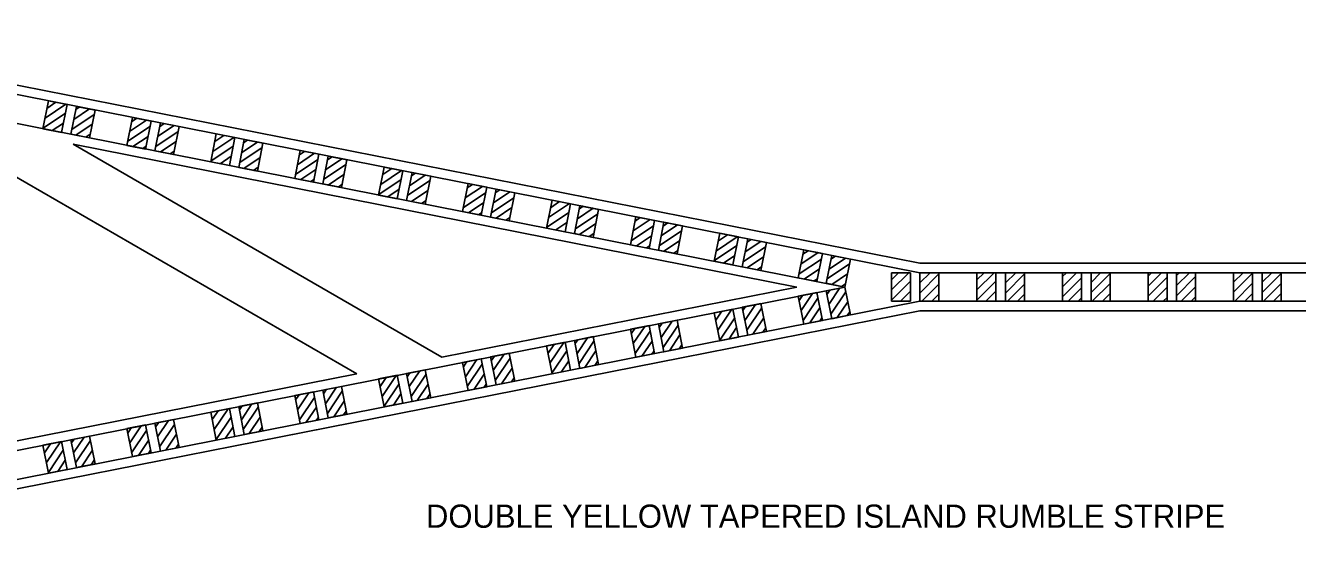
# Model space of a CAD drawing. Extents: x 49976.2 to 50021, y 49987.6 to 50011.4.
# Drawn here: x 50005.455 to 50009.846, y 49993.716 to 49995.521 of the extents above; entities that cross this region are included whole.
import ezdxf

# ---------------------------------------------------------------- set-up
doc = ezdxf.new("R2010")
doc.units = 0
doc.layers.add('Level 1', color=7, linetype='Continuous')
doc.layers.add('Level 2', color=7, linetype='Continuous')

msp = doc.modelspace()

# ---------------------------------------------------------------- linework, layer by layer
at = {"layer": 'Level 1'}
for p, q in [((50008.5427, 49994.7003), (50004.3823, 49995.521)), ((50008.5427, 49994.6675), (50004.3761, 49995.4895)), ((50008.2835, 49994.6183), (50004.357, 49995.3929)), ((50005.0225, 49995.2288), (50006.5989, 49994.3187)), ((50005.5156, 49995.1643), (50005.5347, 49995.2609)), ((50005.5949, 49995.249), (50005.5228, 49995.2007)), ((50005.5607, 49995.2557), (50005.5296, 49995.2349)), ((50005.5347, 49995.2609), (50005.5991, 49995.2482)), ((50005.5991, 49995.2482), (50005.58, 49995.1516)), ((50005.6122, 49995.1453), (50005.6313, 49995.2418)), ((50005.6766, 49995.2329), (50005.6223, 49995.1964)), ((50005.6425, 49995.2396), (50005.629, 49995.2306)), ((50005.6313, 49995.2418), (50005.6956, 49995.2291)), ((50005.6956, 49995.2291), (50005.6766, 49995.1326)), ((50005.5932, 49995.2182), (50005.5161, 49995.1666)), ((50005.6926, 49995.214), (50005.6156, 49995.1623)), ((50005.8053, 49995.1072), (50005.8244, 49995.2037)), ((50005.8736, 49995.194), (50005.8147, 49995.1545)), ((50005.8394, 49995.2008), (50005.8214, 49995.1887)), ((50005.8244, 49995.2037), (50005.8887, 49995.191)), ((50005.8887, 49995.191), (50005.8697, 49995.0945)), ((50005.9019, 49995.0881), (50005.9209, 49995.1847)), ((50005.9209, 49995.1847), (50005.9853, 49995.172)), ((50005.58, 49995.1516), (50005.5156, 49995.1643)), ((50005.5864, 49995.1841), (50005.5475, 49995.158)), ((50005.6766, 49995.1326), (50005.6122, 49995.1453)), ((50005.6859, 49995.1798), (50005.6293, 49995.1419)), ((50005.6792, 49995.1457), (50005.6635, 49995.1352)), ((50005.885, 49995.1721), (50005.8079, 49995.1204)), ((50005.9819, 49995.1549), (50005.9048, 49995.1032)), ((50005.9682, 49995.1754), (50005.9116, 49995.1374)), ((50005.9341, 49995.1821), (50005.9183, 49995.1715)), ((50005.9853, 49995.172), (50005.9662, 49995.0754)), ((50006.095, 49995.05), (50006.114, 49995.1466)), ((50006.1401, 49995.1415), (50006.1089, 49995.1206)), ((50006.114, 49995.1466), (50006.1784, 49995.1339)), ((50008.1174, 49994.6183), (50005.6205, 49995.1109)), ((50005.6205, 49995.1109), (50006.8923, 49994.3766)), ((50005.8697, 49995.0945), (50005.8053, 49995.1072)), ((50005.8783, 49995.1379), (50005.8262, 49995.1031)), ((50005.8715, 49995.1038), (50005.8604, 49995.0963)), ((50005.9752, 49995.1208), (50005.9209, 49995.0844)), ((50006.1725, 49995.104), (50006.0954, 49995.0523)), ((50006.1742, 49995.1347), (50006.1022, 49995.0864)), ((50006.1784, 49995.1339), (50006.1593, 49995.0373)), ((50006.1915, 49995.031), (50006.2106, 49995.1275)), ((50006.272, 49995.0997), (50006.1949, 49995.048)), ((50006.256, 49995.1186), (50006.2016, 49995.0822)), ((50006.2218, 49995.1253), (50006.2084, 49995.1163)), ((50006.2106, 49995.1275), (50006.2749, 49995.1148)), ((50006.2749, 49995.1148), (50006.2559, 49995.0183)), ((50005.9662, 49995.0754), (50005.9019, 49995.0881)), ((50005.9684, 49995.0866), (50005.9551, 49995.0776)), ((50006.1658, 49995.0698), (50006.1269, 49995.0438)), ((50006.2652, 49995.0656), (50006.2086, 49995.0276)), ((50006.3846, 49994.9929), (50006.4037, 49995.0895)), ((50006.4643, 49995.0578), (50006.3872, 49995.0061)), ((50006.4529, 49995.0797), (50006.394, 49995.0403)), ((50006.4187, 49995.0865), (50006.4007, 49995.0744)), ((50006.4037, 49995.0895), (50006.4681, 49995.0768)), ((50006.4681, 49995.0768), (50006.449, 49994.9802)), ((50006.4812, 49994.9739), (50006.5002, 49995.0704)), ((50006.5476, 49995.0611), (50006.4909, 49995.0231)), ((50006.5134, 49995.0678), (50006.4976, 49995.0572)), ((50006.5002, 49995.0704), (50006.5646, 49995.0577)), ((50006.5646, 49995.0577), (50006.5456, 49994.9612)), ((50006.1593, 49995.0373), (50006.095, 49995.05)), ((50006.2559, 49995.0183), (50006.1915, 49995.031)), ((50006.2585, 49995.0314), (50006.2428, 49995.0209)), ((50006.4576, 49995.0237), (50006.4056, 49994.9888)), ((50006.5612, 49995.0406), (50006.4842, 49994.9889)), ((50006.6743, 49994.9358), (50006.6933, 49995.0323)), ((50006.7535, 49995.0204), (50006.6815, 49994.9721)), ((50006.7194, 49995.0272), (50006.6882, 49995.0063)), ((50006.6933, 49995.0323), (50006.7577, 49995.0196)), ((50006.7577, 49995.0196), (50006.7387, 49994.9231)), ((50006.7709, 49994.9167), (50006.7899, 49995.0133)), ((50006.8012, 49995.011), (50006.7877, 49995.002)), ((50006.7899, 49995.0133), (50006.8543, 49995.0006)), ((50006.449, 49994.9802), (50006.3846, 49994.9929)), ((50006.4508, 49994.9895), (50006.4397, 49994.982)), ((50006.5456, 49994.9612), (50006.4812, 49994.9739)), ((50006.5545, 49995.0065), (50006.5002, 49994.9701)), ((50006.5478, 49994.9723), (50006.5344, 49994.9634)), ((50006.7518, 49994.9897), (50006.6747, 49994.938)), ((50006.8513, 49994.9854), (50006.7742, 49994.9337)), ((50006.8353, 49995.0043), (50006.7809, 49994.9679)), ((50006.8543, 49995.0006), (50006.8352, 49994.904)), ((50006.964, 49994.8786), (50006.983, 49994.9752)), ((50007.0322, 49994.9655), (50006.9733, 49994.926)), ((50006.9981, 49994.9722), (50006.98, 49994.9601)), ((50006.983, 49994.9752), (50007.0474, 49994.9625)), ((50006.7387, 49994.9231), (50006.6743, 49994.9358)), ((50006.7451, 49994.9555), (50006.7062, 49994.9295)), ((50006.8445, 49994.9513), (50006.788, 49994.9133)), ((50007.0436, 49994.9435), (50006.9666, 49994.8918)), ((50007.0474, 49994.9625), (50007.0283, 49994.8659)), ((50007.0605, 49994.8596), (50007.0796, 49994.9561)), ((50007.1406, 49994.9263), (50007.0635, 49994.8746)), ((50007.1269, 49994.9468), (50007.0702, 49994.9088)), ((50007.0928, 49994.9535), (50007.077, 49994.9429)), ((50007.0796, 49994.9561), (50007.1439, 49994.9434)), ((50007.1439, 49994.9434), (50007.1249, 49994.8469)), ((50006.8352, 49994.904), (50006.7709, 49994.9167)), ((50006.8378, 49994.9171), (50006.8221, 49994.9066)), ((50007.0283, 49994.8659), (50006.964, 49994.8786)), ((50007.0369, 49994.9094), (50006.9849, 49994.8745)), ((50007.1338, 49994.8922), (50007.0796, 49994.8558)), ((50007.2536, 49994.8215), (50007.2727, 49994.918)), ((50007.3328, 49994.9062), (50007.2608, 49994.8579)), ((50007.2987, 49994.9129), (50007.2675, 49994.892)), ((50007.2727, 49994.918), (50007.337, 49994.9053)), ((50007.337, 49994.9053), (50007.318, 49994.8088)), ((50007.3502, 49994.8024), (50007.3692, 49994.899)), ((50007.4146, 49994.89), (50007.3603, 49994.8536)), ((50007.3805, 49994.8968), (50007.367, 49994.8877)), ((50007.3692, 49994.899), (50007.4336, 49994.8863)), ((50007.4336, 49994.8863), (50007.4145, 49994.7897)), ((50007.0302, 49994.8752), (50007.019, 49994.8678)), ((50007.1249, 49994.8469), (50007.0605, 49994.8596)), ((50007.1271, 49994.858), (50007.1137, 49994.8491)), ((50007.3311, 49994.8754), (50007.2541, 49994.8237)), ((50007.3244, 49994.8413), (50007.2855, 49994.8152)), ((50007.4306, 49994.8711), (50007.3535, 49994.8195)), ((50007.4239, 49994.837), (50007.3673, 49994.799)), ((50007.5433, 49994.7643), (50007.5623, 49994.8609)), ((50007.6115, 49994.8512), (50007.5526, 49994.8117)), ((50007.5774, 49994.8579), (50007.5594, 49994.8458)), ((50007.5623, 49994.8609), (50007.6267, 49994.8482)), ((50007.6267, 49994.8482), (50007.6077, 49994.7516)), ((50007.6398, 49994.7453), (50007.6589, 49994.8418)), ((50007.6721, 49994.8392), (50007.6563, 49994.8286)), ((50007.6589, 49994.8418), (50007.7233, 49994.8291)), ((50007.318, 49994.8088), (50007.2536, 49994.8215)), ((50007.4145, 49994.7897), (50007.3502, 49994.8024)), ((50007.4171, 49994.8028), (50007.4014, 49994.7923)), ((50007.623, 49994.8292), (50007.5459, 49994.7775)), ((50007.6162, 49994.7951), (50007.5642, 49994.7602)), ((50007.7199, 49994.812), (50007.6428, 49994.7604)), ((50007.7062, 49994.8325), (50007.6495, 49994.7945)), ((50007.7233, 49994.8291), (50007.7042, 49994.7326)), ((50007.8329, 49994.7072), (50007.852, 49994.8037)), ((50007.9122, 49994.7919), (50007.8401, 49994.7436)), ((50007.878, 49994.7986), (50007.8469, 49994.7777)), ((50007.852, 49994.8037), (50007.9164, 49994.791)), ((50007.9164, 49994.791), (50007.8973, 49994.6945)), ((50007.6077, 49994.7516), (50007.5433, 49994.7643)), ((50007.6095, 49994.7609), (50007.5983, 49994.7535)), ((50007.7042, 49994.7326), (50007.6398, 49994.7453)), ((50007.7131, 49994.7779), (50007.6589, 49994.7415)), ((50007.9105, 49994.7611), (50007.8334, 49994.7094)), ((50007.9295, 49994.6881), (50007.9486, 49994.7847)), ((50008.0099, 49994.7568), (50007.9329, 49994.7052)), ((50007.9939, 49994.7757), (50007.9396, 49994.7393)), ((50007.9598, 49994.7825), (50007.9463, 49994.7734)), ((50007.9486, 49994.7847), (50008.0129, 49994.772)), ((50008.0129, 49994.772), (50007.9939, 49994.6754)), ((50008.1226, 49994.65), (50008.1417, 49994.7466)), ((50008.1417, 49994.7466), (50008.206, 49994.7339)), ((50007.7064, 49994.7438), (50007.693, 49994.7348)), ((50007.8973, 49994.6945), (50007.8329, 49994.7072)), ((50007.9037, 49994.727), (50007.8648, 49994.7009)), ((50008.0032, 49994.7227), (50007.9466, 49994.6848)), ((50008.2023, 49994.7149), (50008.1252, 49994.6633)), ((50008.1909, 49994.7369), (50008.132, 49994.6974)), ((50008.1567, 49994.7436), (50008.1387, 49994.7315)), ((50008.206, 49994.7339), (50008.187, 49994.6373)), ((50008.2192, 49994.631), (50008.2382, 49994.7276)), ((50008.2855, 49994.7182), (50008.2289, 49994.6802)), ((50008.2514, 49994.7249), (50008.2356, 49994.7144)), ((50008.2382, 49994.7276), (50008.3026, 49994.7149)), ((50008.3026, 49994.7149), (50008.2835, 49994.6183)), ((50007.9939, 49994.6754), (50007.9295, 49994.6881)), ((50007.9965, 49994.6886), (50007.9808, 49994.678)), ((50008.1956, 49994.6808), (50008.1435, 49994.6459)), ((50008.2992, 49994.6977), (50008.2221, 49994.6461)), ((50008.2925, 49994.6636), (50008.2382, 49994.6272)), ((50008.4443, 49994.5691), (50008.4443, 49994.6675)), ((50008.4443, 49994.6675), (50008.5099, 49994.6675)), ((50008.4443, 49994.608), (50008.5038, 49994.6675)), ((50008.4443, 49994.6428), (50008.469, 49994.6675)), ((50008.5099, 49994.6675), (50008.5099, 49994.5691)), ((50008.5427, 49994.7003), (50012.0505, 49994.7003)), ((50008.5427, 49994.6675), (50012.0505, 49994.6675)), ((50008.5427, 49994.5691), (50008.5427, 49994.6675)), ((50008.5427, 49994.6675), (50008.6083, 49994.6675)), ((50008.5427, 49994.6323), (50008.5779, 49994.6675)), ((50008.5427, 49994.6671), (50008.5431, 49994.6675)), ((50008.5427, 49994.5975), (50008.6083, 49994.6632)), ((50008.6083, 49994.6675), (50008.6083, 49994.5691)), ((50008.7395, 49994.5691), (50008.7395, 49994.6675)), ((50008.7395, 49994.6675), (50008.8051, 49994.6675)), ((50008.7395, 49994.608), (50008.799, 49994.6675)), ((50008.7395, 49994.6428), (50008.7642, 49994.6675)), ((50008.8051, 49994.6675), (50008.8051, 49994.5691)), ((50008.8379, 49994.5691), (50008.8379, 49994.6675)), ((50008.8379, 49994.6675), (50008.9035, 49994.6675)), ((50008.8379, 49994.6323), (50008.8731, 49994.6675)), ((50008.8379, 49994.6671), (50008.8383, 49994.6675)), ((50008.8379, 49994.5975), (50008.9035, 49994.6632)), ((50008.9035, 49994.6675), (50008.9035, 49994.5691)), ((50009.0347, 49994.5691), (50009.0347, 49994.6675)), ((50009.0347, 49994.6675), (50009.1004, 49994.6675)), ((50009.0347, 49994.6194), (50009.0829, 49994.6675)), ((50009.0347, 49994.6541), (50009.0481, 49994.6675)), ((50009.1004, 49994.6675), (50009.1004, 49994.5691)), ((50009.1332, 49994.5691), (50009.1332, 49994.6675)), ((50009.1332, 49994.6675), (50009.1988, 49994.6675)), ((50009.1332, 49994.6344), (50009.1663, 49994.6675)), ((50009.1332, 49994.5996), (50009.1988, 49994.6652)), ((50009.1988, 49994.6675), (50009.1988, 49994.5691)), ((50009.33, 49994.5691), (50009.33, 49994.6675)), ((50009.33, 49994.6675), (50009.3956, 49994.6675)), ((50009.33, 49994.6213), (50009.3762, 49994.6675)), ((50009.33, 49994.6561), (50009.3414, 49994.6675)), ((50009.3956, 49994.6675), (50009.3956, 49994.5691)), ((50009.4284, 49994.5691), (50009.4284, 49994.6675)), ((50009.4284, 49994.6675), (50009.494, 49994.6675)), ((50009.4284, 49994.6232), (50009.4727, 49994.6675)), ((50009.4284, 49994.658), (50009.4379, 49994.6675)), ((50009.494, 49994.6675), (50009.494, 49994.5691)), ((50009.6252, 49994.5691), (50009.6252, 49994.6675)), ((50009.6252, 49994.6675), (50009.6908, 49994.6675)), ((50009.6252, 49994.6351), (50009.6577, 49994.6675)), ((50009.6252, 49994.6003), (50009.6908, 49994.6659)), ((50009.6908, 49994.6675), (50009.6908, 49994.5691)), ((50009.7237, 49994.5691), (50009.7237, 49994.6675)), ((50009.7237, 49994.6675), (50009.7893, 49994.6675)), ((50009.7237, 49994.6345), (50009.7567, 49994.6675)), ((50009.7237, 49994.5997), (50009.7893, 49994.6653)), ((50009.7893, 49994.6675), (50009.7893, 49994.5691)), ((50008.2835, 49994.6183), (50004.357, 49993.8437)), ((50008.1174, 49994.6183), (50006.8923, 49994.3766)), ((50008.187, 49994.6373), (50008.1226, 49994.65)), ((50008.1888, 49994.6467), (50008.1777, 49994.6392)), ((50008.2835, 49994.6183), (50008.2192, 49994.631)), ((50008.2192, 49994.6056), (50008.2835, 49994.6183)), ((50008.2665, 49994.6149), (50008.2285, 49994.5583)), ((50008.2857, 49994.6295), (50008.2724, 49994.6205)), ((50008.2835, 49994.6183), (50008.3026, 49994.5217)), ((50008.4443, 49994.5732), (50008.5099, 49994.6388)), ((50008.549, 49994.5691), (50008.6083, 49994.6284)), ((50008.7395, 49994.5732), (50008.8051, 49994.6388)), ((50008.8443, 49994.5691), (50008.9035, 49994.6284)), ((50009.0347, 49994.5846), (50009.1004, 49994.6502)), ((50009.0541, 49994.5691), (50009.1004, 49994.6154)), ((50009.1374, 49994.5691), (50009.1988, 49994.6304)), ((50009.33, 49994.5865), (50009.3956, 49994.6521)), ((50009.3474, 49994.5691), (50009.3956, 49994.6174)), ((50009.4284, 49994.5884), (50009.494, 49994.654)), ((50009.4439, 49994.5691), (50009.494, 49994.6193)), ((50009.6289, 49994.5691), (50009.6908, 49994.6311)), ((50009.7279, 49994.5691), (50009.7893, 49994.6305)), ((50008.1226, 49994.5866), (50008.187, 49994.5993)), ((50008.1417, 49994.49), (50008.1226, 49994.5866)), ((50008.1377, 49994.5895), (50008.1256, 49994.5715)), ((50008.1718, 49994.5963), (50008.1323, 49994.5374)), ((50008.1907, 49994.5803), (50008.1391, 49994.5032)), ((50008.187, 49994.5993), (50008.206, 49994.5027)), ((50008.2382, 49994.509), (50008.2192, 49994.6056)), ((50008.2324, 49994.6082), (50008.2218, 49994.5924)), ((50008.2869, 49994.6012), (50008.2352, 49994.5241)), ((50008.475, 49994.5691), (50008.5099, 49994.604)), ((50008.5838, 49994.5691), (50008.6083, 49994.5936)), ((50008.7702, 49994.5691), (50008.8051, 49994.604)), ((50008.8791, 49994.5691), (50008.9035, 49994.5936)), ((50009.0889, 49994.5691), (50009.1004, 49994.5806)), ((50009.1722, 49994.5691), (50009.1988, 49994.5956)), ((50009.3821, 49994.5691), (50009.3956, 49994.5826)), ((50009.4787, 49994.5691), (50009.494, 49994.5845)), ((50009.6637, 49994.5691), (50009.6908, 49994.5963)), ((50009.7627, 49994.5691), (50009.7893, 49994.5957)), ((50008.5427, 49994.5691), (50004.376, 49993.7471)), ((50008.5427, 49994.5363), (50004.3823, 49993.7156)), ((50007.8329, 49994.5294), (50007.8973, 49994.5421)), ((50007.852, 49994.4329), (50007.8329, 49994.5294)), ((50007.859, 49994.5345), (50007.8381, 49994.5034)), ((50007.8931, 49994.5413), (50007.8448, 49994.4692)), ((50007.8973, 49994.5421), (50007.9164, 49994.4456)), ((50007.9295, 49994.5485), (50007.9939, 49994.5612)), ((50007.9486, 49994.4519), (50007.9295, 49994.5485)), ((50007.9408, 49994.5507), (50007.9317, 49994.5372)), ((50007.9749, 49994.5574), (50007.9385, 49994.5031)), ((50007.9969, 49994.546), (50007.9452, 49994.4689)), ((50007.9939, 49994.5612), (50008.0129, 49994.4646)), ((50008.1975, 49994.5461), (50008.1626, 49994.4941)), ((50008.2936, 49994.5671), (50008.2573, 49994.5128)), ((50008.3004, 49994.5329), (50008.2914, 49994.5195)), ((50008.5099, 49994.5691), (50008.4443, 49994.5691)), ((50008.5098, 49994.5691), (50008.5099, 49994.5692)), ((50008.5427, 49994.5691), (50012.0505, 49994.5691)), ((50008.6083, 49994.5691), (50008.5427, 49994.5691)), ((50008.5427, 49994.5363), (50012.0505, 49994.5363)), ((50008.8051, 49994.5691), (50008.7395, 49994.5691)), ((50008.805, 49994.5691), (50008.8051, 49994.5692)), ((50008.9035, 49994.5691), (50008.8379, 49994.5691)), ((50009.1004, 49994.5691), (50009.0347, 49994.5691)), ((50009.1988, 49994.5691), (50009.1332, 49994.5691)), ((50009.3956, 49994.5691), (50009.33, 49994.5691)), ((50009.494, 49994.5691), (50009.4284, 49994.5691)), ((50009.6908, 49994.5691), (50009.6252, 49994.5691)), ((50009.7893, 49994.5691), (50009.7237, 49994.5691)), ((50007.5433, 49994.4723), (50007.6077, 49994.485)), ((50007.5925, 49994.482), (50007.553, 49994.4231)), ((50007.6077, 49994.485), (50007.6267, 49994.3884)), ((50007.6398, 49994.4913), (50007.7042, 49994.504)), ((50007.6589, 49994.3948), (50007.6398, 49994.4913)), ((50007.653, 49994.4939), (50007.6424, 49994.4781)), ((50007.6872, 49994.5007), (50007.6492, 49994.444)), ((50007.7076, 49994.4869), (50007.6559, 49994.4098)), ((50007.7042, 49994.504), (50007.7233, 49994.4075)), ((50007.9032, 49994.5122), (50007.8516, 49994.4351)), ((50008.0036, 49994.5119), (50007.9657, 49994.4553)), ((50008.206, 49994.5027), (50008.1417, 49994.49)), ((50008.2042, 49994.512), (50008.1967, 49994.5009)), ((50008.3026, 49994.5217), (50008.2382, 49994.509)), ((50007.3502, 49994.4342), (50007.4145, 49994.4469)), ((50007.3956, 49994.4431), (50007.3591, 49994.3888)), ((50007.4145, 49994.4469), (50007.4336, 49994.3503)), ((50007.5623, 49994.3757), (50007.5433, 49994.4723)), ((50007.5583, 49994.4752), (50007.5463, 49994.4572)), ((50007.6114, 49994.466), (50007.5597, 49994.3889)), ((50007.7143, 49994.4528), (50007.6779, 49994.3985)), ((50007.9164, 49994.4456), (50007.852, 49994.4329)), ((50007.91, 49994.478), (50007.8839, 49994.4391)), ((50008.0129, 49994.4646), (50007.9486, 49994.4519)), ((50008.0103, 49994.4777), (50007.9998, 49994.462)), ((50007.2536, 49994.4151), (50007.318, 49994.4278)), ((50007.2727, 49994.3186), (50007.2536, 49994.4151)), ((50007.2797, 49994.4203), (50007.2588, 49994.3891)), ((50007.3138, 49994.427), (50007.2655, 49994.355)), ((50007.3239, 49994.3979), (50007.2722, 49994.3208)), ((50007.318, 49994.4278), (50007.337, 49994.3313)), ((50007.3692, 49994.3376), (50007.3502, 49994.4342)), ((50007.3614, 49994.4364), (50007.3524, 49994.4229)), ((50007.4175, 49994.4317), (50007.3659, 49994.3546)), ((50007.4243, 49994.3976), (50007.3863, 49994.341)), ((50007.6181, 49994.4319), (50007.5832, 49994.3798)), ((50007.6249, 49994.3977), (50007.6174, 49994.3866)), ((50007.7233, 49994.4075), (50007.6589, 49994.3948)), ((50007.7211, 49994.4186), (50007.7121, 49994.4053)), ((50006.964, 49994.358), (50007.0283, 49994.3707)), ((50006.983, 49994.2614), (50006.964, 49994.358)), ((50006.979, 49994.361), (50006.9669, 49994.3429)), ((50007.0132, 49994.3677), (50006.9737, 49994.3088)), ((50007.0321, 49994.3517), (50006.9804, 49994.2746)), ((50007.0283, 49994.3707), (50007.0474, 49994.2741)), ((50007.0605, 49994.377), (50007.1249, 49994.3897)), ((50007.0796, 49994.2805), (50007.0605, 49994.377)), ((50007.0737, 49994.3796), (50007.0631, 49994.3638)), ((50007.1079, 49994.3864), (50007.0699, 49994.3297)), ((50007.1283, 49994.3726), (50007.0766, 49994.2956)), ((50007.1249, 49994.3897), (50007.1439, 49994.2932)), ((50007.3306, 49994.3638), (50007.3046, 49994.3249)), ((50007.4336, 49994.3503), (50007.3692, 49994.3376)), ((50007.431, 49994.3634), (50007.4205, 49994.3477)), ((50007.6267, 49994.3884), (50007.5623, 49994.3757)), ((50006.5989, 49994.3187), (50004.3508, 49993.8752)), ((50006.6743, 49994.3008), (50006.7387, 49994.3135)), ((50006.7345, 49994.3127), (50006.6862, 49994.2407)), ((50006.7387, 49994.3135), (50006.7577, 49994.217)), ((50006.7709, 49994.3199), (50006.8352, 49994.3326)), ((50006.7899, 49994.2233), (50006.7709, 49994.3199)), ((50006.7821, 49994.3221), (50006.7731, 49994.3086)), ((50006.8162, 49994.3288), (50006.7798, 49994.2745)), ((50006.8382, 49994.3174), (50006.7865, 49994.2404)), ((50006.8352, 49994.3326), (50006.8543, 49994.236)), ((50007.0388, 49994.3176), (50007.0039, 49994.2656)), ((50007.135, 49994.3385), (50007.0986, 49994.2842)), ((50007.337, 49994.3313), (50007.2727, 49994.3186)), ((50006.4812, 49994.2627), (50006.5456, 49994.2754)), ((50006.5002, 49994.1662), (50006.4812, 49994.2627)), ((50006.4944, 49994.2653), (50006.4838, 49994.2495)), ((50006.5285, 49994.2721), (50006.4905, 49994.2154)), ((50006.5456, 49994.2754), (50006.5646, 49994.1789)), ((50006.6933, 49994.2043), (50006.6743, 49994.3008)), ((50006.7003, 49994.306), (50006.6794, 49994.2748)), ((50006.7446, 49994.2836), (50006.6929, 49994.2065)), ((50006.8449, 49994.2833), (50006.807, 49994.2267)), ((50007.0474, 49994.2741), (50006.983, 49994.2614)), ((50007.0455, 49994.2834), (50007.0381, 49994.2723)), ((50007.1439, 49994.2932), (50007.0796, 49994.2805)), ((50007.1417, 49994.3044), (50007.1328, 49994.291)), ((50006.1915, 49994.2056), (50006.2559, 49994.2183)), ((50006.2559, 49994.2183), (50006.2749, 49994.1217)), ((50006.3846, 49994.2437), (50006.449, 49994.2564)), ((50006.4037, 49994.1471), (50006.3846, 49994.2437)), ((50006.3997, 49994.2467), (50006.3876, 49994.2286)), ((50006.4338, 49994.2534), (50006.3943, 49994.1945)), ((50006.4527, 49994.2374), (50006.4011, 49994.1604)), ((50006.449, 49994.2564), (50006.4681, 49994.1598)), ((50006.5489, 49994.2583), (50006.4973, 49994.1813)), ((50006.5557, 49994.2242), (50006.5193, 49994.1699)), ((50006.7513, 49994.2495), (50006.7252, 49994.2106)), ((50006.8543, 49994.236), (50006.7899, 49994.2233)), ((50006.8517, 49994.2492), (50006.8411, 49994.2334)), ((50006.095, 49994.1866), (50006.1593, 49994.1993)), ((50006.114, 49994.09), (50006.095, 49994.1866)), ((50006.121, 49994.1917), (50006.1001, 49994.1605)), ((50006.1551, 49994.1984), (50006.1068, 49994.1264)), ((50006.1593, 49994.1993), (50006.1784, 49994.1027)), ((50006.2106, 49994.109), (50006.1915, 49994.2056)), ((50006.2028, 49994.2078), (50006.1937, 49994.1943)), ((50006.2369, 49994.2146), (50006.2005, 49994.1602)), ((50006.2589, 49994.2031), (50006.2072, 49994.1261)), ((50006.4595, 49994.2033), (50006.4246, 49994.1513)), ((50006.5646, 49994.1789), (50006.5002, 49994.1662)), ((50006.5624, 49994.1901), (50006.5534, 49994.1767)), ((50006.7577, 49994.217), (50006.6933, 49994.2043)), ((50005.8053, 49994.1294), (50005.8697, 49994.1421)), ((50005.8204, 49994.1324), (50005.8083, 49994.1144)), ((50005.8545, 49994.1391), (50005.815, 49994.0802)), ((50005.8697, 49994.1421), (50005.8887, 49994.0456)), ((50005.9019, 49994.1485), (50005.9662, 49994.1612)), ((50005.9209, 49994.0519), (50005.9019, 49994.1485)), ((50005.9151, 49994.1511), (50005.9045, 49994.1353)), ((50005.9492, 49994.1578), (50005.9112, 49994.1011)), ((50005.9696, 49994.1441), (50005.9179, 49994.067)), ((50005.9662, 49994.1612), (50005.9853, 49994.0646)), ((50006.1652, 49994.1693), (50006.1136, 49994.0923)), ((50006.172, 49994.1352), (50006.1459, 49994.0963)), ((50006.2656, 49994.169), (50006.2277, 49994.1124)), ((50006.2724, 49994.1349), (50006.2618, 49994.1192)), ((50006.4681, 49994.1598), (50006.4037, 49994.1471)), ((50006.4662, 49994.1692), (50006.4587, 49994.158)), ((50005.6122, 49994.0913), (50005.6766, 49994.104)), ((50005.6313, 49993.9948), (50005.6122, 49994.0913)), ((50005.6235, 49994.0935), (50005.6144, 49994.0801)), ((50005.6576, 49994.1003), (50005.6212, 49994.0459)), ((50005.6796, 49994.0889), (50005.6279, 49994.0118)), ((50005.6766, 49994.104), (50005.6956, 49994.0075)), ((50005.8244, 49994.0329), (50005.8053, 49994.1294)), ((50005.8734, 49994.1231), (50005.8218, 49994.0461)), ((50005.8802, 49994.089), (50005.8453, 49994.037)), ((50005.9763, 49994.1099), (50005.94, 49994.0557)), ((50006.1784, 49994.1027), (50006.114, 49994.09)), ((50006.2749, 49994.1217), (50006.2106, 49994.109)), ((50005.5156, 49994.0723), (50005.58, 49994.085)), ((50005.5347, 49993.9757), (50005.5156, 49994.0723)), ((50005.5417, 49994.0774), (50005.5208, 49994.0462)), ((50005.5758, 49994.0841), (50005.5275, 49994.0121)), ((50005.5859, 49994.055), (50005.5343, 49993.978)), ((50005.58, 49994.085), (50005.5991, 49993.9884)), ((50005.6863, 49994.0547), (50005.6484, 49993.9981)), ((50005.8887, 49994.0456), (50005.8244, 49994.0329)), ((50005.8869, 49994.0549), (50005.8794, 49994.0437)), ((50005.9853, 49994.0646), (50005.9209, 49994.0519)), ((50005.9831, 49994.0758), (50005.9741, 49994.0624)), ((50005.5927, 49994.0209), (50005.5666, 49993.982)), ((50005.6956, 49994.0075), (50005.6313, 49993.9948)), ((50005.693, 49994.0206), (50005.6825, 49994.0049)), ((50005.5991, 49993.9884), (50005.5347, 49993.9757))]:
    msp.add_line(p, q, dxfattribs=at)

# ---------------------------------------------------------------- texts
at = {"layer": 'Level 2'}
msp.add_text('DOUBLE YELLOW TAPERED ISLAND RUMBLE STRIPE', height=0.08, dxfattribs=at).set_placement((50006.8377, 49993.7874))

doc.saveas('drawing.dxf')
